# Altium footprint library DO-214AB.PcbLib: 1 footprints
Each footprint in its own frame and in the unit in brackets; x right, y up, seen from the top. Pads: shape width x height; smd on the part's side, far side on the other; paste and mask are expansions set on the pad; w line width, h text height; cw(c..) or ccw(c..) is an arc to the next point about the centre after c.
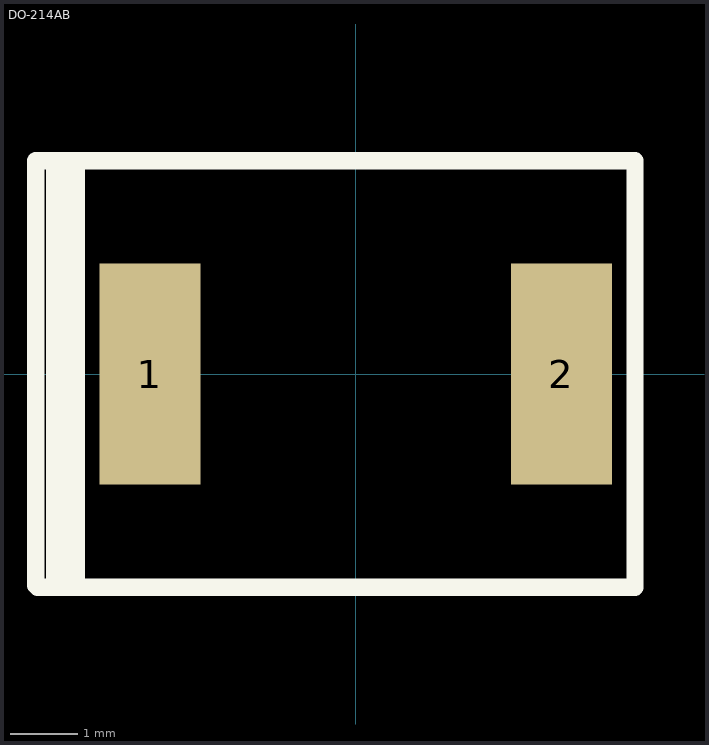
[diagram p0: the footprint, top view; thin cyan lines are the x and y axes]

## DO-214AB [mm] "FAIRCHILD DO-0214AB"
height 2.7
pads (2):
  rect 1.49x3.27 smd: 1(-3.04,0) 2(3.04,0)
Top Overlay:
  lines w0.254: -4.475,-3.15 -4.45,-3.125 -4.45,3.1 ; -4.3,-2.975 -4.3,3.15 ; -4.725,-3.125 -4.725,3.15 ; -4.725,-3.125 -4.7,-3.15 -4.125,-3.15 ; -4.725,-3.125 -4.725,3.15 ; -4.725,3.15 -4.125,3.15 ; -4.125,-3.15 4.125,-3.15 4.125,3.15 -4.125,3.15 ; -4.125,-3.15 -4.125,3.15
M5 Assembly Top:
  text ".Designator" at 0,0 h1.02
3D body: height 2.7, standoff 0, extent -4.125,-3.175 4.1,3.125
